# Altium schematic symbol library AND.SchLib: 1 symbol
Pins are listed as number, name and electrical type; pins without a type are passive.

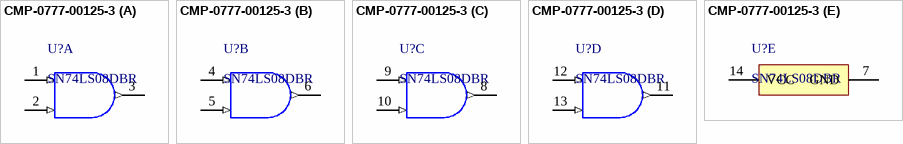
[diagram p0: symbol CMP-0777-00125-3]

## CMP-0777-00125-3
designator U?, comment SN74LS08DBR
Quadruple 2-Input Positive-AND Gates, DB0014A, LARGE T&R; Manufacturer: Texas Instruments; F @ Nom Voltage(Max)(Mhz): 35; Output Type: TTL; VCC(Min)(V): 4.75; Output Drive (IOL/IOH)(Max)(mA): -0.8/16; Voltage(Nom)(V): 5; VCC(Max)(V): 5.25; Schmitt Trigger: No; Technology Family: LS; ICC @ Nom Voltage(Max)(mA): 0.021; tpd @ Nom Voltage(Max)(ns): 25; Rating: Catalog; Bits(#): 4
footprint DB0014A_M (SOP, 14-Leads, Body 5.6x6.5mm, Pitch 0.65mm, IPC Low Density)
footprint DB0014A_N (SOP, 14-Leads, Body 5.6x6.5mm, Pitch 0.65mm, IPC Medium Density)
footprint DB0014A_L (SOP, 14-Leads, Body 5.6x6.5mm, Pitch 0.65mm, IPC High Density)
part A pins: 1 1A (in), 2 1B (in), 3 1Y (out)
part B pins: 4 2A (in), 5 2B (in), 6 2Y (out)
part C pins: 8 3Y (out), 9 3A (in), 10 3B (in)
part D pins: 11 4Y (out), 12 4A (in), 13 4B (in)
part E pins: 7 GND (power), 14 VCC (power)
